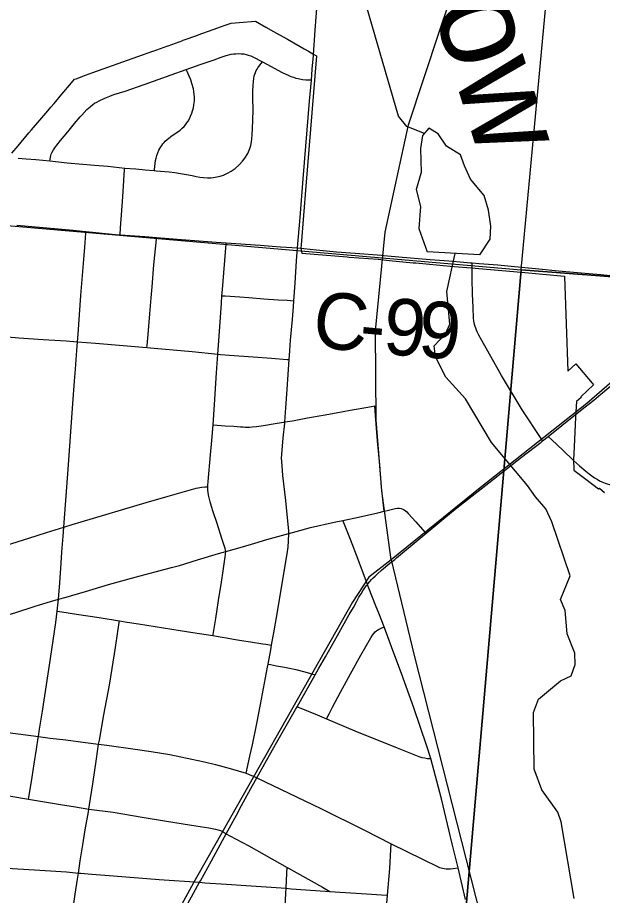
# Model space of a CAD drawing. Extents: x -1.4 to 35.4, y 0 to 22.
# Drawn here: x 19.497 to 20.085, y 17.179 to 18.063 of the extents above; entities that cross this region are included whole.
import ezdxf

# ---------------------------------------------------------------- set-up
doc = ezdxf.new("R2010")
doc.units = 0
for name, color, linetype in [('GM_X_City_Street', 7, 'Continuous'), ('GM_X_Corporation', 7, 'Continuous'), ('GM_X_County_Road', 7, 'Continuous'), ('GM_X_County_Road_Text', 7, 'Continuous'), ('GM_X_Minor_Lake', 7, 'Continuous'), ('GM_X_Minor_River', 7, 'Continuous'), ('GM_X_Minor_River_Text', 7, 'Continuous'), ('GM_X_Rail_Line', 7, 'Continuous'), ('GM_X_Section', 7, 'Continuous'), ('GM_X_State_Route', 7, 'Continuous'), ('GM_X_US_Route', 7, 'Continuous')]:
    doc.layers.add(name, color=color, linetype=linetype)

msp = doc.modelspace()

# ---------------------------------------------------------------- linework, layer by layer
at = {"layer": 'GM_X_City_Street'}
for points in [[(19.52922, 17.91854), (19.5295, 17.92005), (19.52996, 17.92255), (19.53033, 17.92394), (19.53071, 17.92542), (19.53154, 17.92737), (19.53284, 17.92969), (19.53426, 17.93173), (19.53533, 17.93309), (19.5363, 17.93433), (19.54012, 17.9392), (19.54728, 17.94793), (19.55413, 17.95627), (19.55964, 17.96298), (19.56138, 17.96473), (19.5664, 17.9702), (19.56982, 17.97315), (19.57246, 17.97537), (19.57436, 17.97668), (19.57649, 17.97788), (19.57881, 17.97923), (19.58465, 17.98187), (19.58962, 17.98381), (19.59372, 17.98531), (19.60497, 17.98888), (19.62418, 17.99564), (19.63833, 18.00062), (19.65114, 18.00534), (19.66649, 18.01059), (19.68042, 18.01556), (19.69441, 18.02047), (19.70144, 18.02292), (19.70671, 18.02473), (19.7115, 18.02597), (19.71395, 18.02635), (19.71626, 18.02654), (19.71904, 18.02673), (19.72173, 18.02654), (19.72432, 18.02626), (19.72664, 18.0258), (19.7287, 18.02516), (19.73128, 18.02432), (19.73334, 18.02339), (19.74313, 18.0182), (19.74761, 18.01582), (19.76299, 18.0077), (19.76969, 18.0045), (19.77178, 18.00356), (19.77431, 18.00276), (19.77669, 18.00198), (19.77904, 18.00141), (19.78337, 18.00069), (19.7868, 18.00031), (19.79134, 18.00013), (19.79231, 18.00003)], [(19.4974, 17.92132), (19.50557, 17.9207), (19.51519, 17.91997), (19.52922, 17.91854), (19.54655, 17.91677), (19.56252, 17.91544), (19.57429, 17.91439), (19.58752, 17.9132), (19.60482, 17.91145), (19.6158, 17.9105), (19.62505, 17.90971), (19.63436, 17.90892), (19.63618, 17.90877), (19.64914, 17.90761), (19.6551, 17.90681), (19.66081, 17.90594), (19.66681, 17.90492), (19.67233, 17.90382), (19.6763, 17.90301), (19.68018, 17.9024), (19.68389, 17.90196), (19.6879, 17.90165), (19.69159, 17.90175), (19.6956, 17.90227), (19.70045, 17.90323), (19.70393, 17.90439), (19.70794, 17.90618), (19.71158, 17.90825), (19.71563, 17.91111), (19.71982, 17.91476), (19.72319, 17.91837), (19.72544, 17.92134), (19.72831, 17.92607), (19.73042, 17.93117), (19.73128, 17.93411), (19.73201, 17.93785), (19.7323, 17.94035), (19.73274, 17.94514), (19.73314, 17.951), (19.73366, 17.96934), (19.73335, 17.98228), (19.73354, 17.98896), (19.73371, 17.99452), (19.73405, 17.99864), (19.73434, 18.00169), (19.73482, 18.00415), (19.73545, 18.00604), (19.73599, 18.00773), (19.73695, 18.0096), (19.73774, 18.01087), (19.73861, 18.01213), (19.73963, 18.01371), (19.7419, 18.01669), (19.74313, 18.0182)], [(19.63436, 17.90892), (19.6345, 17.91), (19.63563, 17.91901), (19.63623, 17.92141), (19.63697, 17.92418), (19.63795, 17.9269), (19.63904, 17.92943), (19.63989, 17.93125), (19.64075, 17.93273), (19.64182, 17.93429), (19.64289, 17.93569), (19.64412, 17.93717), (19.64542, 17.93849), (19.64712, 17.94002), (19.64897, 17.94153), (19.65023, 17.94256), (19.65103, 17.94309), (19.65341, 17.94473), (19.65812, 17.94788), (19.66048, 17.94959), (19.66245, 17.95143), (19.66426, 17.9532), (19.66587, 17.95505), (19.66722, 17.9569), (19.66837, 17.95861), (19.66977, 17.96109), (19.6709, 17.9636), (19.67207, 17.9666), (19.6728, 17.96887), (19.67363, 17.97219), (19.67412, 17.97495), (19.6747, 17.97901), (19.67478, 17.98304), (19.67453, 17.98534), (19.6742, 17.98847), (19.67371, 17.99104), (19.6722, 17.99644), (19.671, 18.00014), (19.66952, 18.00376), (19.6673, 18.00869), (19.66649, 18.01059)], [(19.59996, 17.84436), (19.60042, 17.85117), (19.6013, 17.86423), (19.60254, 17.88252), (19.60365, 17.89892), (19.6044, 17.90991), (19.60482, 17.91145)], [(19.53812, 17.47742), (19.53924, 17.49408), (19.54055, 17.51387), (19.54139, 17.525), (19.5426, 17.54114), (19.54326, 17.55004), (19.54794, 17.61272), (19.55135, 17.66047), (19.55272, 17.67897), (19.55404, 17.69682), (19.55501, 17.70901), (19.55652, 17.72793), (19.55706, 17.73659), (19.55762, 17.74429), (19.56047, 17.78307), (19.56305, 17.81548), (19.56433, 17.83166), (19.56545, 17.84575), (19.5656, 17.84763)], [(19.62686, 17.73084), (19.62704, 17.73274), (19.62805, 17.74377), (19.62999, 17.7648), (19.63129, 17.7808), (19.63222, 17.79191), (19.63399, 17.81407), (19.63646, 17.83988), (19.63661, 17.84151)], [(19.7064, 17.52555), (19.7055, 17.52842), (19.7023, 17.53872), (19.69749, 17.55364), (19.69368, 17.56549), (19.69196, 17.57083), (19.69058, 17.57538), (19.68982, 17.57831), (19.68924, 17.58086), (19.68867, 17.58448), (19.68833, 17.58746), (19.68817, 17.58982), (19.68822, 17.59064), (19.68828, 17.59196), (19.68858, 17.5959), (19.69095, 17.62291), (19.6923, 17.63711), (19.6934, 17.65291), (19.69483, 17.67347), (19.69704, 17.70542), (19.69834, 17.72418), (19.69897, 17.73316), (19.70088, 17.76089), (19.70188, 17.77545), (19.7024, 17.78297), (19.70283, 17.78925), (19.70653, 17.83511), (19.70674, 17.83607)], [(20.02487, 17.63682), (20.02334, 17.63914), (20.00429, 17.6682), (19.98352, 17.7027), (19.96083, 17.74313), (19.95939, 17.74582), (19.95824, 17.74845), (19.95759, 17.75018), (19.95701, 17.7519), (19.95668, 17.75313), (19.95619, 17.75535), (19.95578, 17.75774), (19.95553, 17.76029), (19.95495, 17.77105), (19.9543, 17.78478), (19.95397, 17.79977), (19.95393, 17.80696), (19.95392, 17.81599)], [(19.7024, 17.78297), (19.70578, 17.78273), (19.7203, 17.7817), (19.72929, 17.78106), (19.74459, 17.77997), (19.75887, 17.77895), (19.76783, 17.77831), (19.7747, 17.77783)], [(19.45314, 17.74328), (19.46245, 17.74276), (19.48686, 17.74157), (19.49798, 17.74066), (19.52248, 17.73903), (19.54002, 17.7378), (19.54554, 17.73743), (19.55706, 17.73659), (19.57513, 17.73526), (19.62686, 17.73084), (19.63414, 17.73022), (19.67238, 17.72677), (19.69834, 17.72418), (19.70098, 17.72387), (19.71008, 17.7232), (19.73387, 17.72144), (19.75233, 17.72006), (19.76783, 17.71891), (19.76992, 17.71877)], [(19.6934, 17.65291), (19.70561, 17.65211), (19.71421, 17.65153), (19.72105, 17.65108), (19.72383, 17.65089), (19.72586, 17.6508), (19.72993, 17.6508), (19.7328, 17.65089), (19.73714, 17.65133), (19.74408, 17.65247), (19.75807, 17.65471), (19.76474, 17.65578), (19.76558, 17.65592), (19.77324, 17.65716), (19.78852, 17.65997), (19.80424, 17.66285), (19.81724, 17.66523), (19.83145, 17.66769), (19.84124, 17.66938), (19.85285, 17.67139), (19.85607, 17.672)], [(19.86544, 17.56613), (19.86507, 17.56908), (19.86289, 17.5902), (19.86109, 17.61282), (19.85894, 17.63682), (19.85682, 17.66237), (19.85607, 17.672)], [(19.47299, 17.52769), (19.47585, 17.52865), (19.48577, 17.53196), (19.50817, 17.53903), (19.52587, 17.54461), (19.54326, 17.55004), (19.55187, 17.55265), (19.56064, 17.55531), (19.62614, 17.57474), (19.64813, 17.58139), (19.67628, 17.58924), (19.68207, 17.59025), (19.6851, 17.5905), (19.68822, 17.59064)], [(19.94739, 17.17535), (19.93983, 17.20714), (19.93398, 17.2313), (19.92304, 17.27677), (19.9125, 17.31722), (19.9086, 17.32965), (19.89538, 17.36829), (19.88303, 17.40267), (19.87437, 17.42592), (19.8654, 17.44969), (19.86017, 17.46356), (19.85758, 17.46978), (19.84957, 17.49023), (19.84871, 17.49244), (19.83925, 17.51762), (19.83168, 17.53777), (19.82444, 17.55597), (19.82408, 17.55688)], [(19.69329, 17.44089), (19.69345, 17.44188), (19.69614, 17.45798), (19.69897, 17.47624), (19.70181, 17.49456), (19.70361, 17.50593), (19.70469, 17.51304), (19.70578, 17.52023), (19.7064, 17.52555)], [(19.50789, 17.27628), (19.50817, 17.27811), (19.5114, 17.29845), (19.51355, 17.31202), (19.51589, 17.32672), (19.51767, 17.33797), (19.51786, 17.33924), (19.51902, 17.34687), (19.52177, 17.36492), (19.52978, 17.41788), (19.53526, 17.45401), (19.53666, 17.46548), (19.53812, 17.47742)], [(19.53666, 17.46548), (19.54145, 17.46475), (19.55625, 17.46251), (19.5789, 17.45898), (19.5992, 17.45578), (19.60709, 17.45454), (19.61857, 17.45273), (19.66023, 17.44606), (19.67312, 17.44399), (19.69329, 17.44089), (19.70254, 17.43946), (19.70682, 17.43876), (19.71413, 17.43745), (19.72207, 17.43607), (19.73122, 17.43463), (19.74342, 17.43265), (19.74649, 17.43215), (19.75237, 17.43119)], [(19.54744, 17.13022), (19.54811, 17.13468), (19.55056, 17.15115), (19.55281, 17.16661), (19.55489, 17.18075), (19.55713, 17.19588), (19.55803, 17.20191), (19.55986, 17.21425), (19.56246, 17.2305), (19.56484, 17.24533), (19.56802, 17.26359), (19.56845, 17.26631), (19.56914, 17.27073), (19.5724, 17.29182), (19.57625, 17.31675), (19.57833, 17.33166), (19.57908, 17.33563), (19.58372, 17.36127), (19.58913, 17.39115), (19.5918, 17.40788), (19.5952, 17.42907), (19.59894, 17.45403), (19.5992, 17.45578)], [(19.80747, 17.3572), (19.81015, 17.36234), (19.8135, 17.3688), (19.82144, 17.38407), (19.83153, 17.40228), (19.84204, 17.42122), (19.85201, 17.43858), (19.85387, 17.44139), (19.85521, 17.4431), (19.85649, 17.44456), (19.85809, 17.44592), (19.85991, 17.44695), (19.86182, 17.4479), (19.8654, 17.44969)], [(19.74891, 17.41209), (19.7512, 17.41168), (19.75739, 17.41058), (19.76518, 17.40918), (19.77038, 17.4081), (19.77654, 17.4067), (19.78566, 17.40433), (19.79374, 17.40212), (19.7961, 17.40153)], [(19.77793, 17.36934), (19.78168, 17.36781), (19.79814, 17.36111), (19.80747, 17.3572), (19.83619, 17.34521), (19.87848, 17.32794), (19.90043, 17.31923), (19.90335, 17.31836), (19.90636, 17.31773), (19.90927, 17.31736), (19.9125, 17.31722)], [(19.48688, 17.34348), (19.505, 17.3409), (19.51786, 17.33924), (19.52962, 17.33772), (19.54521, 17.33585), (19.56523, 17.33345), (19.57833, 17.33166), (19.58649, 17.33055), (19.61497, 17.32659), (19.63122, 17.32413), (19.64983, 17.32111), (19.67224, 17.31662), (19.68479, 17.31383), (19.69588, 17.31108), (19.7107, 17.30729), (19.72681, 17.3024)], [(19.36941, 17.29178), (19.38505, 17.29054), (19.40218, 17.28919), (19.42466, 17.28742), (19.44141, 17.28589), (19.45239, 17.28488), (19.46522, 17.28306), (19.47742, 17.28137), (19.4901, 17.27933), (19.50789, 17.27628), (19.51391, 17.27524), (19.53997, 17.27098), (19.55505, 17.26851), (19.56845, 17.26631), (19.59296, 17.26318), (19.62197, 17.25822), (19.64458, 17.25436), (19.67169, 17.25017), (19.68905, 17.24749), (19.6958, 17.24616), (19.7009, 17.24466), (19.70372, 17.24336), (19.70662, 17.24141)], [(19.73756, 17.2979), (19.80196, 17.26677), (19.84565, 17.24495), (19.87259, 17.2315), (19.91992, 17.20822), (19.92132, 17.20768), (19.92282, 17.20717), (19.92424, 17.20684), (19.92581, 17.2066), (19.92773, 17.20634), (19.92973, 17.20626), (19.93231, 17.20626), (19.93481, 17.20651), (19.93983, 17.20714)], [(19.70662, 17.24141), (19.71019, 17.2395), (19.72942, 17.22921), (19.76809, 17.20765), (19.76922, 17.20702), (19.8036, 17.18758), (19.81098, 17.18338)], [(19.86481, 17.13145), (19.86748, 17.16307), (19.86888, 17.17956), (19.87117, 17.20654), (19.87227, 17.22567), (19.87259, 17.2315)], [(19.39393, 17.21263), (19.405, 17.21198), (19.41637, 17.21145), (19.43418, 17.2106), (19.44515, 17.2099), (19.44727, 17.20983), (19.46373, 17.20865), (19.4861, 17.20675), (19.5139, 17.20502), (19.5461, 17.20302), (19.55803, 17.20191), (19.56032, 17.20169), (19.57145, 17.20084), (19.59336, 17.19916), (19.63909, 17.1955), (19.6798, 17.19266)], [(19.72542, 16.59796), (19.72893, 16.64508), (19.73275, 16.6964), (19.73308, 16.70094), (19.73651, 16.75231), (19.73966, 16.7955), (19.74141, 16.81961), (19.74493, 16.86218), (19.74746, 16.89268), (19.74969, 16.92769), (19.75207, 16.968), (19.75381, 16.99765), (19.75655, 17.04045), (19.75909, 17.07329), (19.76255, 17.11591), (19.76468, 17.14462), (19.76668, 17.18142), (19.76696, 17.18662), (19.76779, 17.20192), (19.76809, 17.20765)], [(19.6798, 17.19266), (19.68522, 17.19226), (19.70702, 17.19068), (19.72688, 17.18933), (19.76696, 17.18662), (19.77188, 17.18619), (19.79632, 17.18428), (19.81098, 17.18338), (19.8478, 17.18095), (19.86298, 17.17994), (19.86888, 17.17956)]]:
    msp.add_lwpolyline(points, dxfattribs=at)
at = {"layer": 'GM_X_Corporation'}
msp.add_lwpolyline([(19.49109, 17.92647), (19.49741, 17.93392), (19.50827, 17.94674), (19.51093, 17.94987), (19.51095, 17.9499), (19.51929, 17.95975), (19.51929, 17.95974), (19.52728, 17.96917), (19.53032, 17.97275), (19.53348, 17.97648), (19.54133, 17.98575), (19.55114, 17.99732), (19.55409, 18.00081), (19.5557, 18.00138), (19.56516, 18.00479), (19.57266, 18.00749), (19.58771, 18.01292), (19.60277, 18.01833), (19.61783, 18.02375), (19.63294, 18.02902), (19.63328, 18.02914), (19.648, 18.03444), (19.64834, 18.03456), (19.66306, 18.03986), (19.6634, 18.03998), (19.67811, 18.04528), (19.67846, 18.0454), (19.69346, 18.0508), (19.70547, 18.05512), (19.7116, 18.05733), (19.7198, 18.05802), (19.73596, 18.05938), (19.74655, 18.05336), (19.75432, 18.04895), (19.76032, 18.04555), (19.76832, 18.041), (19.7809, 18.03387), (19.78504, 18.03152), (19.78505, 18.03151), (19.78935, 18.02907), (19.79227, 18.02741), (19.79389, 18.02649), (19.79752, 18.02443), (19.78685, 17.89304), (19.78206, 17.83403), (19.78179, 17.83077), (19.7826, 17.82582), (19.82821, 17.82196), (19.83028, 17.82181), (19.85939, 17.81971), (19.87061, 17.81834), (19.89483, 17.81617), (19.89748, 17.81601), (19.93179, 17.81283), (19.94864, 17.81134), (19.95336, 17.81093), (19.96065, 17.81028), (20.00326, 17.80651), (20.04694, 17.80265), (20.04695, 17.80239), (20.05029, 17.70697), (20.0582, 17.71433), (20.07473, 17.69492), (20.0754, 17.69414), (20.07613, 17.69328), (20.06317, 17.68121), (20.06366, 17.68064), (20.05891, 17.67644), (20.05802, 17.66073), (20.05633, 17.62344), (20.05608, 17.61834), (20.05616, 17.60746), (20.06825, 17.59823), (20.08106, 17.58846), (20.08193, 17.58942), (20.08718, 17.58482)], dxfattribs=at)
at = {"layer": 'GM_X_County_Road'}
msp.add_line((19.86544, 17.56613), (19.86844, 17.56684), dxfattribs=at)
for points in [[(19.79443, 18.02454), (19.79451, 18.02552), (19.79615, 18.05016), (19.79738, 18.06752), (19.8013, 18.11769), (19.80495, 18.15979), (19.80778, 18.19731)], [(19.79231, 18.00003), (19.79325, 18.01084), (19.79443, 18.02454)], [(19.77839, 17.83102), (19.78108, 17.86162), (19.78406, 17.90051), (19.78658, 17.93346), (19.79047, 17.97868), (19.79231, 18.00003)], [(19.49624, 17.85395), (19.55274, 17.84889), (19.5656, 17.84763)], [(19.5656, 17.84763), (19.59541, 17.8447), (19.59996, 17.84436)], [(19.59996, 17.84436), (19.62488, 17.84248), (19.63661, 17.84151)], [(19.63661, 17.84151), (19.66156, 17.83944), (19.69665, 17.83676), (19.70674, 17.83607)], [(19.70674, 17.83607), (19.74074, 17.83372), (19.75277, 17.83282), (19.76117, 17.83219), (19.77839, 17.83102)], [(19.7747, 17.77783), (19.77601, 17.79562), (19.77752, 17.81817), (19.77839, 17.83102)], [(19.77839, 17.83102), (19.79739, 17.8292), (19.81749, 17.82727), (19.83646, 17.82572), (19.86295, 17.82365), (19.8651, 17.82347), (19.88385, 17.82184), (19.9118, 17.81941), (19.93042, 17.81792), (19.94553, 17.81672), (19.95248, 17.81612), (19.95392, 17.81599)], [(19.95392, 17.81599), (19.9612, 17.81535), (19.97999, 17.81387), (19.99318, 17.8127), (20.02115, 17.80985)], [(20.02115, 17.80985), (20.04089, 17.808), (20.05968, 17.80616), (20.08342, 17.80427), (20.09266, 17.80346), (20.11126, 17.80192), (20.13783, 17.79972), (20.15133, 17.7986), (20.17058, 17.79677), (20.17332, 17.79647), (20.17594, 17.79619), (20.17907, 17.79566), (20.18202, 17.79501), (20.18445, 17.79409), (20.18667, 17.79296), (20.18969, 17.79098)], [(19.76992, 17.71877), (19.77055, 17.72742), (19.77145, 17.73831), (19.77317, 17.75912), (19.77427, 17.7721), (19.7747, 17.77783)], [(19.76558, 17.65592), (19.76671, 17.67003), (19.76755, 17.68381), (19.7692, 17.7088), (19.76992, 17.71877)], [(19.76647, 17.57678), (19.76369, 17.60207), (19.76262, 17.61652), (19.76238, 17.61955), (19.76271, 17.62301), (19.76308, 17.62767), (19.76401, 17.64005), (19.76548, 17.6548), (19.76558, 17.65592)], [(19.76971, 17.54369), (19.76949, 17.54606), (19.76722, 17.56997), (19.76647, 17.57678)], [(19.82408, 17.55688), (19.8398, 17.56024), (19.85899, 17.56449), (19.86544, 17.56613)], [(19.86844, 17.56684), (19.87654, 17.56885), (19.87902, 17.56922), (19.88104, 17.56913), (19.88278, 17.56876), (19.88416, 17.5683), (19.88572, 17.56747), (19.8871, 17.56647), (19.88838, 17.56536), (19.88967, 17.5639), (19.89726, 17.55548), (19.90657, 17.54516), (19.90775, 17.54389)], [(19.76971, 17.54369), (19.78066, 17.54672), (19.79129, 17.54985), (19.81532, 17.55501), (19.82408, 17.55688)], [(19.7064, 17.52555), (19.72289, 17.53009), (19.7353, 17.53385), (19.74744, 17.53752), (19.76971, 17.54369)], [(19.75237, 17.43119), (19.755, 17.44577), (19.7573, 17.45928), (19.75927, 17.47084), (19.76705, 17.51739), (19.76795, 17.5232), (19.76887, 17.52979), (19.76938, 17.53637), (19.76971, 17.54369)], [(19.53812, 17.47742), (19.5456, 17.4795), (19.56526, 17.48531), (19.58823, 17.49225), (19.61494, 17.49983), (19.63531, 17.50515), (19.65173, 17.50944), (19.65964, 17.51153), (19.67773, 17.51699), (19.69896, 17.5235), (19.7064, 17.52555)], [(19.5146, 17.4706), (19.51882, 17.47198), (19.53005, 17.47517), (19.53812, 17.47742)], [(19.46759, 17.4558), (19.48508, 17.46106), (19.49509, 17.46418), (19.5146, 17.4706)], [(19.74891, 17.41209), (19.75154, 17.42661), (19.75237, 17.43119)], [(19.72681, 17.3024), (19.73056, 17.31962), (19.73305, 17.33105), (19.73758, 17.35254), (19.74117, 17.37148), (19.74526, 17.39301), (19.74835, 17.40921), (19.74891, 17.41209)], [(19.72681, 17.3024), (19.73197, 17.30026), (19.73656, 17.29835), (19.73756, 17.2979)]]:
    msp.add_lwpolyline(points, dxfattribs=at)
at = {"layer": 'GM_X_Minor_Lake'}
for points in [[(19.96161, 17.82403), (19.97214, 17.83976), (19.97278, 17.85303), (19.97045, 17.86902), (19.9662, 17.88391), (19.95252, 17.90014), (19.94635, 17.91356), (19.94241, 17.92465), (19.9282, 17.93329), (19.91975, 17.94599), (19.91039, 17.9515), (19.90419, 17.94404), (19.90204, 17.93118), (19.9027, 17.90687), (19.89782, 17.88989), (19.90202, 17.87272), (19.90045, 17.85073), (19.90868, 17.82703)], [(19.96161, 17.82403), (19.90868, 17.82703)]]:
    msp.add_lwpolyline(points, dxfattribs=at)
at = {"layer": 'GM_X_Minor_River'}
for points in [[(19.9061, 17.94634), (19.88848, 17.95309), (19.87998, 17.96352), (19.83784, 18.1094), (19.82957, 18.13158), (19.79873, 18.16031), (19.78314, 18.19479), (19.76816, 18.24133)], [(20.05664, 17.17649), (20.0434, 17.25341), (20.04019, 17.26335), (20.02398, 17.28569), (20.01644, 17.30634), (20.01569, 17.36365), (20.02087, 17.37683), (20.0428, 17.39535), (20.0535, 17.40044), (20.05751, 17.41174), (20.05736, 17.42313), (20.04942, 17.44265), (20.04761, 17.46621), (20.04291, 17.47732), (20.05247, 17.50103), (20.03424, 17.5553), (20.02806, 17.56834), (20.01771, 17.5807), (20.00961, 17.59187), (19.97338, 17.63514), (19.94738, 17.67933), (19.92738, 17.701), (19.91718, 17.72133), (19.91589, 17.73236), (19.92711, 17.74466), (19.93146, 17.75443), (19.92871, 17.78714), (19.93692, 17.82543)]]:
    msp.add_lwpolyline(points, dxfattribs=at)
at = {"layer": 'GM_X_Rail_Line'}
for points in [[(19.87253, 17.51702), (19.86331, 17.58646), (19.85761, 17.6579), (19.85691, 17.74768), (19.86638, 17.84706), (19.8899, 17.9549), (19.92128, 18.04927), (19.94802, 18.12919), (20.00142, 18.24978), (20.10807, 18.45366), (20.23881, 18.7072), (20.28696, 18.80067)], [(20.68795, 18.76646), (20.2308, 17.86617), (20.19188, 17.79669), (20.16565, 17.76443), (20.12705, 17.72456), (20.06922, 17.67454), (19.9621, 17.58978), (19.87253, 17.51702)], [(19.87253, 17.51702), (19.85018, 17.49982), (19.83351, 17.47456), (19.67363, 17.19196), (19.47348, 16.8265), (19.36455, 16.60749), (19.23623, 16.32838), (19.09718, 15.99152), (19.04133, 15.85765), (19.02649, 15.81572), (18.99433, 15.72097), (18.97662, 15.63287), (18.89804, 15.26632)], [(19.87253, 17.51702), (19.89569, 17.42086), (20.03387, 16.87789), (20.09282, 16.66531), (20.11533, 16.57157), (20.12436, 16.49098), (20.12216, 16.43154), (20.10886, 16.35009), (20.08419, 16.2702), (20.0556, 16.21257), (20.0082, 16.1358), (19.95838, 16.07), (19.88832, 15.99109), (19.77863, 15.87245), (19.67544, 15.76065), (19.6249, 15.69972), (19.57477, 15.61937), (19.54045, 15.53532), (19.50697, 15.40358), (19.47895, 15.28596)]]:
    msp.add_lwpolyline(points, dxfattribs=at)
at = {"layer": 'GM_X_Section'}
for points in [[(21.07664, 18.26569), (21.03748, 17.72984), (20.00335, 17.80912), (20.09738, 18.81836), (21.11068, 18.73155), (21.0858, 18.39111)], [(20.66207, 17.75862), (21.03748, 17.72984), (20.95168, 16.72111), (19.91613, 16.79977), (20.00335, 17.80912), (20.64022, 17.76029)]]:
    msp.add_lwpolyline(points, dxfattribs=at)
msp.add_lwpolyline([(20.00335, 17.80912), (19.91613, 16.79977), (18.89767, 16.8845), (18.98115, 17.8973)], close=True, dxfattribs=at)
at = {"layer": 'GM_X_State_Route'}
for points in [[(20.03054, 17.64134), (20.03429, 17.63783), (20.04529, 17.62753), (20.05611, 17.61722)], [(20.05611, 17.61722), (20.06212, 17.61181), (20.06843, 17.60635), (20.07172, 17.6036), (20.07451, 17.60154), (20.0771, 17.59979), (20.07964, 17.59826), (20.08223, 17.59681), (20.08431, 17.59577), (20.08607, 17.59493), (20.08786, 17.59417), (20.08986, 17.5935), (20.09199, 17.59285), (20.09416, 17.59225), (20.09643, 17.5917), (20.09883, 17.59119), (20.10138, 17.59077), (20.10316, 17.59053)]]:
    msp.add_lwpolyline(points, dxfattribs=at)
at = {"layer": 'GM_X_US_Route'}
for points in [[(20.05807, 17.66331), (20.06775, 17.67113), (20.07628, 17.678), (20.08349, 17.68382), (20.08507, 17.68514), (20.11083, 17.70711), (20.12455, 17.71885), (20.13179, 17.72538), (20.13656, 17.73031), (20.14951, 17.74323), (20.16082, 17.7557), (20.17408, 17.7714), (20.18969, 17.79098)], [(19.94634, 17.57537), (19.97088, 17.59468), (20.00369, 17.62031), (20.02331, 17.63557), (20.02487, 17.63682), (20.03054, 17.64134), (20.05807, 17.66331)], [(19.84478, 17.48701), (19.8454, 17.488), (19.84748, 17.49092), (19.84871, 17.49244), (19.84926, 17.49312), (19.85114, 17.49533), (19.85295, 17.49731), (19.85452, 17.49912), (19.85633, 17.50084), (19.85877, 17.50303), (19.86285, 17.50664), (19.8712, 17.51371), (19.8761, 17.51761), (19.87788, 17.51902), (19.90174, 17.53892), (19.90775, 17.54389), (19.93526, 17.56665), (19.94634, 17.57537)], [(19.71853, 17.26335), (19.72043, 17.26686), (19.73317, 17.29011), (19.73756, 17.2979), (19.74731, 17.31519), (19.75773, 17.33381), (19.7695, 17.35483), (19.7763, 17.36654), (19.77793, 17.36934), (19.78305, 17.37816), (19.79144, 17.39319), (19.7961, 17.40153), (19.79946, 17.40755), (19.80663, 17.41962), (19.81852, 17.44093), (19.83048, 17.46216), (19.83463, 17.46934), (19.83757, 17.47479), (19.83871, 17.47688), (19.84018, 17.47948), (19.84138, 17.48143), (19.84228, 17.48299), (19.84417, 17.48603), (19.84478, 17.48701)], [(19.55602, 16.9677), (19.55929, 16.97381), (19.56252, 16.97998), (19.56602, 16.98671), (19.57511, 17.00346), (19.58404, 17.01946), (19.59871, 17.04576), (19.60144, 17.05084), (19.6125, 17.07055), (19.62122, 17.08668), (19.62771, 17.09819), (19.63293, 17.10745), (19.64043, 17.12073), (19.64171, 17.12308), (19.65375, 17.14515), (19.66211, 17.16012), (19.6798, 17.19266), (19.68065, 17.19424), (19.69174, 17.21416), (19.70302, 17.23478), (19.70662, 17.24141), (19.71853, 17.26335)]]:
    msp.add_lwpolyline(points, dxfattribs=at)

# ---------------------------------------------------------------- texts
at = {"layer": 'GM_X_County_Road_Text'}
for s, rotation, p in [('C', 353.86066, (19.79193, 17.73181)), ('9', 355.34802, (19.86317, 17.72453)), ('9', 355.76001, (19.8985, 17.72166)), ('-', 354.7518, (19.83929, 17.72672))]:
    msp.add_text(s, height=0.05682, rotation=rotation, dxfattribs=at).set_placement(p)
at = {"layer": 'GM_X_Minor_River_Text'}
msp.add_text('Yellow', height=0.094769, rotation=287.17588, dxfattribs=at).set_placement((19.85202, 18.27482))

doc.saveas('drawing.dxf')
